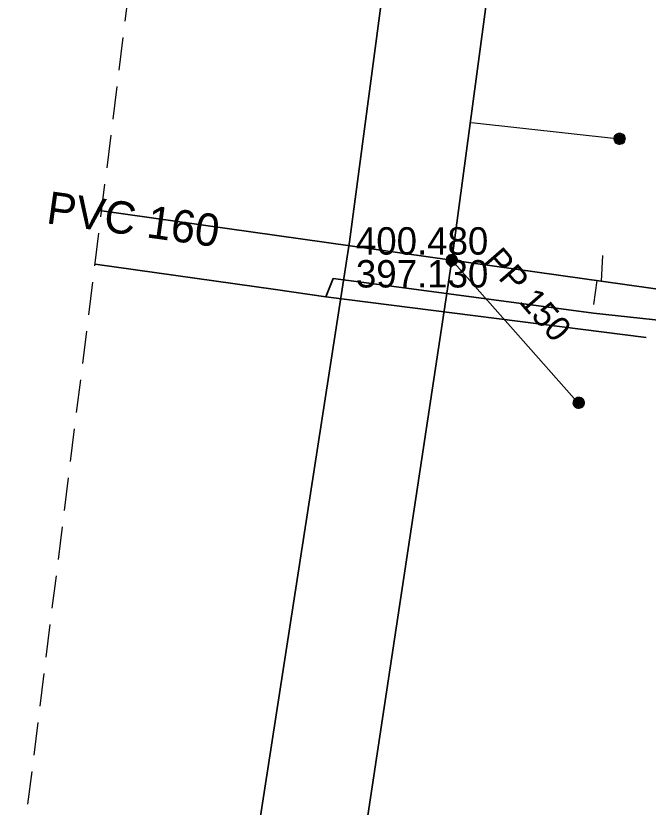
# Model space of a CAD drawing. Extents: x -866761 to -866592, y -1013996 to -1013877.
# Drawn here: x -866760.58 to -866735.18, y -1013979.48 to -1013947.7 of the extents above; entities that cross this region are included whole.
import ezdxf

# ---------------------------------------------------------------- set-up
doc = ezdxf.new("R2010")
doc.units = 0
doc.header["$LTSCALE"] = 0.44
doc.linetypes.add('MEDIUM_DASHED', pattern=[4.5, 3, -1.5])
for name, color, linetype, lineweight in [('1', 7, 'Continuous', 35), ('21', 7, 'Continuous', 35), ('23', 7, 'Continuous', 25), ('25', 7, 'Continuous', 13), ('32', 7, 'Continuous', 13), ('62', 7, 'MEDIUM_DASHED', 25)]:
    doc.layers.add(name, color=color, linetype=linetype, lineweight=lineweight)

msp = doc.modelspace()

# ---------------------------------------------------------------- linework, layer by layer
at = {"layer": '1'}
for p, q in [((-866750.15, -1013958.69), (-866757.398, -1013957.672)), ((-866735.26, -1013960.62), (-866748.13, -1013958.99))]:
    msp.add_line(p, q, dxfattribs=at)
for points in [[(-866751.412, -1013984.065), (-866747.177, -1013956.779), (-866736.629, -1013877.301)], [(-866612.815, -1013977.108), (-866621.035, -1013976.325), (-866621.378, -1013976.297), (-866626.243, -1013975.519), (-866632.94, -1013974.51), (-866645.03, -1013972.86), (-866647.305, -1013972.501), (-866654.48, -1013971.31), (-866668.882, -1013969.171), (-866678.229, -1013967.78), (-866685.446, -1013966.718), (-866689.8, -1013966.06), (-866697.865, -1013964.927), (-866723.097, -1013961.352), (-866726.923, -1013960.77), (-866727.214, -1013960.734), (-866737.38, -1013959.64), (-866746.09, -1013958.48), (-866747.84, -1013958.25), (-866748.13, -1013958.99), (-866750.15, -1013958.69)]]:
    msp.add_lwpolyline(points, dxfattribs=at)
at = {"layer": '21'}
for p, q in [((-866743.067, -1013957.51), (-866737.854, -1013918.522)), ((-866757.131, -1013955.526), (-866743.07, -1013957.51)), ((-866747.14, -1013984.43), (-866743.067, -1013957.51)), ((-866743.07, -1013957.51), (-866709.04, -1013962.31))]:
    msp.add_line(p, q, dxfattribs=at)
at = {"layer": '23'}
for p, q in [((-866742.284, -1013951.979), (-866736.33, -1013952.64)), ((-866743.07, -1013957.51), (-866737.95, -1013963.3)), ((-866737.054, -1013958.359), (-866736.996, -1013957.329)), ((-866737.244, -1013958.332), (-866737.381, -1013959.294))]:
    msp.add_line(p, q, dxfattribs=at)
at = {"layer": '25'}
for points in [[(-866736.098, -1013952.64), (-866736.105, -1013952.588), (-866736.122, -1013952.538), (-866736.151, -1013952.494), (-866736.188, -1013952.457), (-866736.233, -1013952.43), (-866736.282, -1013952.413), (-866736.336, -1013952.409), (-866736.387, -1013952.416), (-866736.436, -1013952.435), (-866736.48, -1013952.464), (-866736.516, -1013952.503), (-866736.542, -1013952.548), (-866736.558, -1013952.599), (-866736.561, -1013952.651), (-866736.553, -1013952.703), (-866736.532, -1013952.752), (-866736.502, -1013952.795), (-866736.463, -1013952.829), (-866736.417, -1013952.855), (-866736.365, -1013952.869), (-866736.313, -1013952.871), (-866736.262, -1013952.861), (-866736.213, -1013952.84), (-866736.171, -1013952.809), (-866736.137, -1013952.768), (-866736.113, -1013952.722), (-866736.1, -1013952.671)], [(-866736.129, -1013952.64), (-866736.135, -1013952.591), (-866736.152, -1013952.545), (-866736.179, -1013952.505), (-866736.217, -1013952.473), (-866736.261, -1013952.451), (-866736.309, -1013952.44), (-866736.358, -1013952.44), (-866736.404, -1013952.453), (-866736.448, -1013952.477), (-866736.483, -1013952.51), (-866736.511, -1013952.551), (-866736.527, -1013952.598), (-866736.531, -1013952.647), (-866736.524, -1013952.695), (-866736.505, -1013952.74), (-866736.475, -1013952.78), (-866736.436, -1013952.811), (-866736.392, -1013952.831), (-866736.345, -1013952.841), (-866736.296, -1013952.839), (-866736.249, -1013952.824), (-866736.206, -1013952.799), (-866736.171, -1013952.765), (-866736.146, -1013952.723), (-866736.132, -1013952.676)], [(-866736.159, -1013952.64), (-866736.164, -1013952.595), (-866736.181, -1013952.553), (-866736.21, -1013952.518), (-866736.245, -1013952.491), (-866736.288, -1013952.474), (-866736.333, -1013952.469), (-866736.377, -1013952.475), (-866736.419, -1013952.494), (-866736.453, -1013952.522), (-866736.48, -1013952.559), (-866736.497, -1013952.601), (-866736.5, -1013952.646), (-866736.494, -1013952.691), (-866736.475, -1013952.732), (-866736.446, -1013952.766), (-866736.409, -1013952.792), (-866736.365, -1013952.808), (-866736.321, -1013952.811), (-866736.276, -1013952.803), (-866736.235, -1013952.783), (-866736.201, -1013952.754), (-866736.176, -1013952.716), (-866736.162, -1013952.673)], [(-866736.189, -1013952.64), (-866736.193, -1013952.599), (-866736.212, -1013952.562), (-866736.239, -1013952.531), (-866736.274, -1013952.51), (-866736.314, -1013952.499), (-866736.355, -1013952.501), (-866736.394, -1013952.514), (-866736.428, -1013952.538), (-866736.453, -1013952.57), (-866736.468, -1013952.608), (-866736.47, -1013952.649), (-866736.463, -1013952.689), (-866736.443, -1013952.725), (-866736.414, -1013952.754), (-866736.377, -1013952.773), (-866736.337, -1013952.781), (-866736.296, -1013952.777), (-866736.257, -1013952.762), (-866736.225, -1013952.736), (-866736.203, -1013952.702), (-866736.19, -1013952.663)], [(-866736.218, -1013952.64), (-866736.223, -1013952.604), (-866736.242, -1013952.572), (-866736.267, -1013952.547), (-866736.301, -1013952.532), (-866736.338, -1013952.529), (-866736.372, -1013952.537), (-866736.404, -1013952.557), (-866736.426, -1013952.585), (-866736.44, -1013952.619), (-866736.44, -1013952.656), (-866736.429, -1013952.691), (-866736.407, -1013952.72), (-866736.377, -1013952.741), (-866736.343, -1013952.751), (-866736.306, -1013952.749), (-866736.272, -1013952.735), (-866736.245, -1013952.712), (-866736.225, -1013952.68), (-866736.218, -1013952.645)], [(-866736.249, -1013952.64), (-866736.254, -1013952.609), (-866736.271, -1013952.583), (-866736.296, -1013952.566), (-866736.326, -1013952.559), (-866736.358, -1013952.563), (-866736.385, -1013952.58), (-866736.402, -1013952.604), (-866736.411, -1013952.635), (-866736.407, -1013952.665), (-866736.392, -1013952.693), (-866736.367, -1013952.712), (-866736.338, -1013952.721), (-866736.306, -1013952.718), (-866736.279, -1013952.704), (-866736.259, -1013952.68), (-866736.249, -1013952.651)], [(-866736.279, -1013952.64), (-866736.284, -1013952.616), (-866736.301, -1013952.598), (-866736.323, -1013952.589), (-866736.348, -1013952.592), (-866736.369, -1013952.606), (-866736.38, -1013952.628), (-866736.38, -1013952.653), (-866736.367, -1013952.674), (-866736.348, -1013952.688), (-866736.323, -1013952.691), (-866736.299, -1013952.682), (-866736.284, -1013952.664)], [(-866736.309, -1013952.64), (-866736.314, -1013952.625), (-866736.328, -1013952.619), (-866736.343, -1013952.623), (-866736.35, -1013952.637), (-866736.347, -1013952.652), (-866736.333, -1013952.661), (-866736.318, -1013952.658), (-866736.309, -1013952.646)], [(-866737.739, -1013963.24), (-866737.745, -1013963.188), (-866737.762, -1013963.138), (-866737.791, -1013963.094), (-866737.828, -1013963.057), (-866737.873, -1013963.03), (-866737.923, -1013963.013), (-866737.976, -1013963.009), (-866738.027, -1013963.016), (-866738.076, -1013963.035), (-866738.12, -1013963.064), (-866738.156, -1013963.103), (-866738.182, -1013963.148), (-866738.198, -1013963.199), (-866738.201, -1013963.251), (-866738.193, -1013963.303), (-866738.173, -1013963.352), (-866738.142, -1013963.395), (-866738.103, -1013963.429), (-866738.057, -1013963.455), (-866738.005, -1013963.469), (-866737.953, -1013963.471), (-866737.902, -1013963.461), (-866737.853, -1013963.44), (-866737.811, -1013963.409), (-866737.777, -1013963.368), (-866737.753, -1013963.322), (-866737.74, -1013963.271)], [(-866737.769, -1013963.24), (-866737.775, -1013963.191), (-866737.792, -1013963.145), (-866737.82, -1013963.105), (-866737.857, -1013963.073), (-866737.901, -1013963.051), (-866737.949, -1013963.04), (-866737.998, -1013963.04), (-866738.044, -1013963.053), (-866738.088, -1013963.077), (-866738.124, -1013963.11), (-866738.151, -1013963.151), (-866738.167, -1013963.198), (-866738.171, -1013963.247), (-866738.164, -1013963.295), (-866738.145, -1013963.34), (-866738.115, -1013963.38), (-866738.076, -1013963.411), (-866738.032, -1013963.431), (-866737.985, -1013963.441), (-866737.936, -1013963.439), (-866737.889, -1013963.424), (-866737.846, -1013963.399), (-866737.811, -1013963.365), (-866737.786, -1013963.323), (-866737.772, -1013963.276)], [(-866737.799, -1013963.24), (-866737.804, -1013963.195), (-866737.821, -1013963.153), (-866737.85, -1013963.118), (-866737.886, -1013963.091), (-866737.928, -1013963.074), (-866737.973, -1013963.069), (-866738.017, -1013963.075), (-866738.059, -1013963.094), (-866738.093, -1013963.122), (-866738.12, -1013963.159), (-866738.137, -1013963.201), (-866738.141, -1013963.246), (-866738.134, -1013963.291), (-866738.115, -1013963.332), (-866738.086, -1013963.366), (-866738.049, -1013963.392), (-866738.005, -1013963.408), (-866737.961, -1013963.411), (-866737.916, -1013963.403), (-866737.875, -1013963.383), (-866737.842, -1013963.354), (-866737.816, -1013963.316), (-866737.802, -1013963.273)], [(-866737.829, -1013963.24), (-866737.833, -1013963.199), (-866737.852, -1013963.162), (-866737.879, -1013963.131), (-866737.914, -1013963.11), (-866737.954, -1013963.099), (-866737.995, -1013963.101), (-866738.034, -1013963.114), (-866738.068, -1013963.138), (-866738.093, -1013963.17), (-866738.108, -1013963.208), (-866738.11, -1013963.249), (-866738.103, -1013963.289), (-866738.083, -1013963.325), (-866738.054, -1013963.354), (-866738.017, -1013963.373), (-866737.977, -1013963.381), (-866737.936, -1013963.377), (-866737.897, -1013963.362), (-866737.865, -1013963.336), (-866737.843, -1013963.302), (-866737.83, -1013963.263)], [(-866737.858, -1013963.24), (-866737.864, -1013963.204), (-866737.882, -1013963.172), (-866737.907, -1013963.147), (-866737.941, -1013963.132), (-866737.978, -1013963.129), (-866738.012, -1013963.137), (-866738.044, -1013963.157), (-866738.066, -1013963.185), (-866738.08, -1013963.219), (-866738.08, -1013963.256), (-866738.069, -1013963.291), (-866738.048, -1013963.32), (-866738.017, -1013963.341), (-866737.983, -1013963.351), (-866737.946, -1013963.349), (-866737.912, -1013963.335), (-866737.885, -1013963.312), (-866737.865, -1013963.28), (-866737.858, -1013963.245)], [(-866737.889, -1013963.24), (-866737.894, -1013963.209), (-866737.911, -1013963.183), (-866737.936, -1013963.166), (-866737.967, -1013963.159), (-866737.998, -1013963.163), (-866738.025, -1013963.18), (-866738.043, -1013963.204), (-866738.051, -1013963.235), (-866738.047, -1013963.265), (-866738.032, -1013963.293), (-866738.007, -1013963.312), (-866737.978, -1013963.321), (-866737.946, -1013963.318), (-866737.919, -1013963.304), (-866737.899, -1013963.28), (-866737.889, -1013963.251)], [(-866737.919, -1013963.24), (-866737.924, -1013963.216), (-866737.941, -1013963.198), (-866737.963, -1013963.189), (-866737.988, -1013963.192), (-866738.009, -1013963.206), (-866738.02, -1013963.228), (-866738.02, -1013963.253), (-866738.007, -1013963.274), (-866737.988, -1013963.288), (-866737.963, -1013963.291), (-866737.94, -1013963.282), (-866737.924, -1013963.264)], [(-866737.949, -1013963.24), (-866737.954, -1013963.225), (-866737.968, -1013963.219), (-866737.983, -1013963.223), (-866737.99, -1013963.237), (-866737.987, -1013963.252), (-866737.973, -1013963.261), (-866737.958, -1013963.258), (-866737.949, -1013963.246)]]:
    msp.add_lwpolyline(points, close=True, dxfattribs=at)
at = {"layer": '32'}
for points in [[(-866742.838, -1013957.51), (-866742.845, -1013957.458), (-866742.862, -1013957.408), (-866742.891, -1013957.364), (-866742.928, -1013957.327), (-866742.973, -1013957.3), (-866743.022, -1013957.283), (-866743.076, -1013957.279), (-866743.127, -1013957.286), (-866743.176, -1013957.305), (-866743.22, -1013957.334), (-866743.255, -1013957.373), (-866743.282, -1013957.418), (-866743.298, -1013957.469), (-866743.301, -1013957.521), (-866743.293, -1013957.573), (-866743.272, -1013957.622), (-866743.242, -1013957.665), (-866743.203, -1013957.699), (-866743.157, -1013957.725), (-866743.105, -1013957.739), (-866743.053, -1013957.741), (-866743.002, -1013957.731), (-866742.953, -1013957.71), (-866742.911, -1013957.679), (-866742.877, -1013957.638), (-866742.853, -1013957.592), (-866742.84, -1013957.541)], [(-866742.869, -1013957.51), (-866742.875, -1013957.461), (-866742.892, -1013957.415), (-866742.919, -1013957.375), (-866742.956, -1013957.343), (-866743, -1013957.321), (-866743.049, -1013957.31), (-866743.098, -1013957.31), (-866743.144, -1013957.323), (-866743.188, -1013957.347), (-866743.223, -1013957.38), (-866743.25, -1013957.421), (-866743.267, -1013957.468), (-866743.271, -1013957.517), (-866743.264, -1013957.565), (-866743.245, -1013957.61), (-866743.215, -1013957.65), (-866743.176, -1013957.681), (-866743.132, -1013957.701), (-866743.085, -1013957.711), (-866743.036, -1013957.709), (-866742.989, -1013957.694), (-866742.946, -1013957.669), (-866742.911, -1013957.635), (-866742.886, -1013957.593), (-866742.872, -1013957.546)], [(-866742.899, -1013957.51), (-866742.904, -1013957.465), (-866742.921, -1013957.423), (-866742.95, -1013957.388), (-866742.985, -1013957.361), (-866743.027, -1013957.344), (-866743.073, -1013957.339), (-866743.117, -1013957.345), (-866743.159, -1013957.364), (-866743.193, -1013957.392), (-866743.22, -1013957.429), (-866743.237, -1013957.471), (-866743.24, -1013957.516), (-866743.233, -1013957.561), (-866743.215, -1013957.602), (-866743.186, -1013957.636), (-866743.149, -1013957.662), (-866743.105, -1013957.678), (-866743.061, -1013957.681), (-866743.016, -1013957.673), (-866742.975, -1013957.653), (-866742.941, -1013957.624), (-866742.916, -1013957.586), (-866742.902, -1013957.543)], [(-866742.929, -1013957.51), (-866742.933, -1013957.469), (-866742.951, -1013957.432), (-866742.978, -1013957.401), (-866743.014, -1013957.38), (-866743.054, -1013957.369), (-866743.095, -1013957.371), (-866743.134, -1013957.384), (-866743.168, -1013957.408), (-866743.193, -1013957.44), (-866743.208, -1013957.478), (-866743.21, -1013957.519), (-866743.203, -1013957.559), (-866743.183, -1013957.595), (-866743.154, -1013957.624), (-866743.117, -1013957.643), (-866743.076, -1013957.651), (-866743.036, -1013957.647), (-866742.997, -1013957.632), (-866742.965, -1013957.606), (-866742.943, -1013957.572), (-866742.929, -1013957.533)], [(-866742.958, -1013957.51), (-866742.963, -1013957.474), (-866742.982, -1013957.442), (-866743.007, -1013957.417), (-866743.041, -1013957.402), (-866743.078, -1013957.399), (-866743.112, -1013957.407), (-866743.144, -1013957.427), (-866743.166, -1013957.455), (-866743.179, -1013957.489), (-866743.179, -1013957.526), (-866743.169, -1013957.561), (-866743.147, -1013957.59), (-866743.117, -1013957.611), (-866743.083, -1013957.621), (-866743.046, -1013957.619), (-866743.012, -1013957.605), (-866742.985, -1013957.582), (-866742.965, -1013957.55), (-866742.958, -1013957.515)], [(-866742.989, -1013957.51), (-866742.994, -1013957.479), (-866743.011, -1013957.453), (-866743.036, -1013957.436), (-866743.066, -1013957.429), (-866743.098, -1013957.433), (-866743.125, -1013957.45), (-866743.142, -1013957.474), (-866743.151, -1013957.505), (-866743.147, -1013957.535), (-866743.132, -1013957.563), (-866743.107, -1013957.582), (-866743.078, -1013957.591), (-866743.046, -1013957.588), (-866743.019, -1013957.574), (-866742.999, -1013957.55), (-866742.989, -1013957.521)], [(-866743.019, -1013957.51), (-866743.024, -1013957.486), (-866743.041, -1013957.468), (-866743.063, -1013957.459), (-866743.088, -1013957.462), (-866743.108, -1013957.476), (-866743.12, -1013957.498), (-866743.12, -1013957.523), (-866743.107, -1013957.544), (-866743.088, -1013957.558), (-866743.063, -1013957.561), (-866743.039, -1013957.552), (-866743.024, -1013957.534)], [(-866743.049, -1013957.51), (-866743.054, -1013957.495), (-866743.068, -1013957.489), (-866743.083, -1013957.493), (-866743.09, -1013957.507), (-866743.087, -1013957.522), (-866743.073, -1013957.531), (-866743.058, -1013957.528), (-866743.049, -1013957.516)]]:
    msp.add_lwpolyline(points, close=True, dxfattribs=at)
at = {"layer": '62'}
msp.add_lwpolyline([(-866747.317, -1013876.568), (-866591.969, -1013887.219), (-866617.09, -1013995.541), (-866760.581, -1013983.282)], close=True, dxfattribs=at)

# ---------------------------------------------------------------- texts
at = {"layer": '1'}
msp.add_text('PVC 160 ', height=1.3, rotation=352, dxfattribs=at).set_placement((-866759.392, -1013956.027))
at = {"layer": '23'}
msp.add_text('PP 150', height=1, rotation=311, dxfattribs=at).set_placement((-866741.823, -1013957.561))
at = {"layer": '25'}
for s, p in [('400.480 ', (-866746.92, -1013957.29)), ('397.130 ', (-866746.92, -1013958.61))]:
    msp.add_text(s, height=1.1, dxfattribs=at).set_placement(p)

doc.saveas('drawing.dxf')
